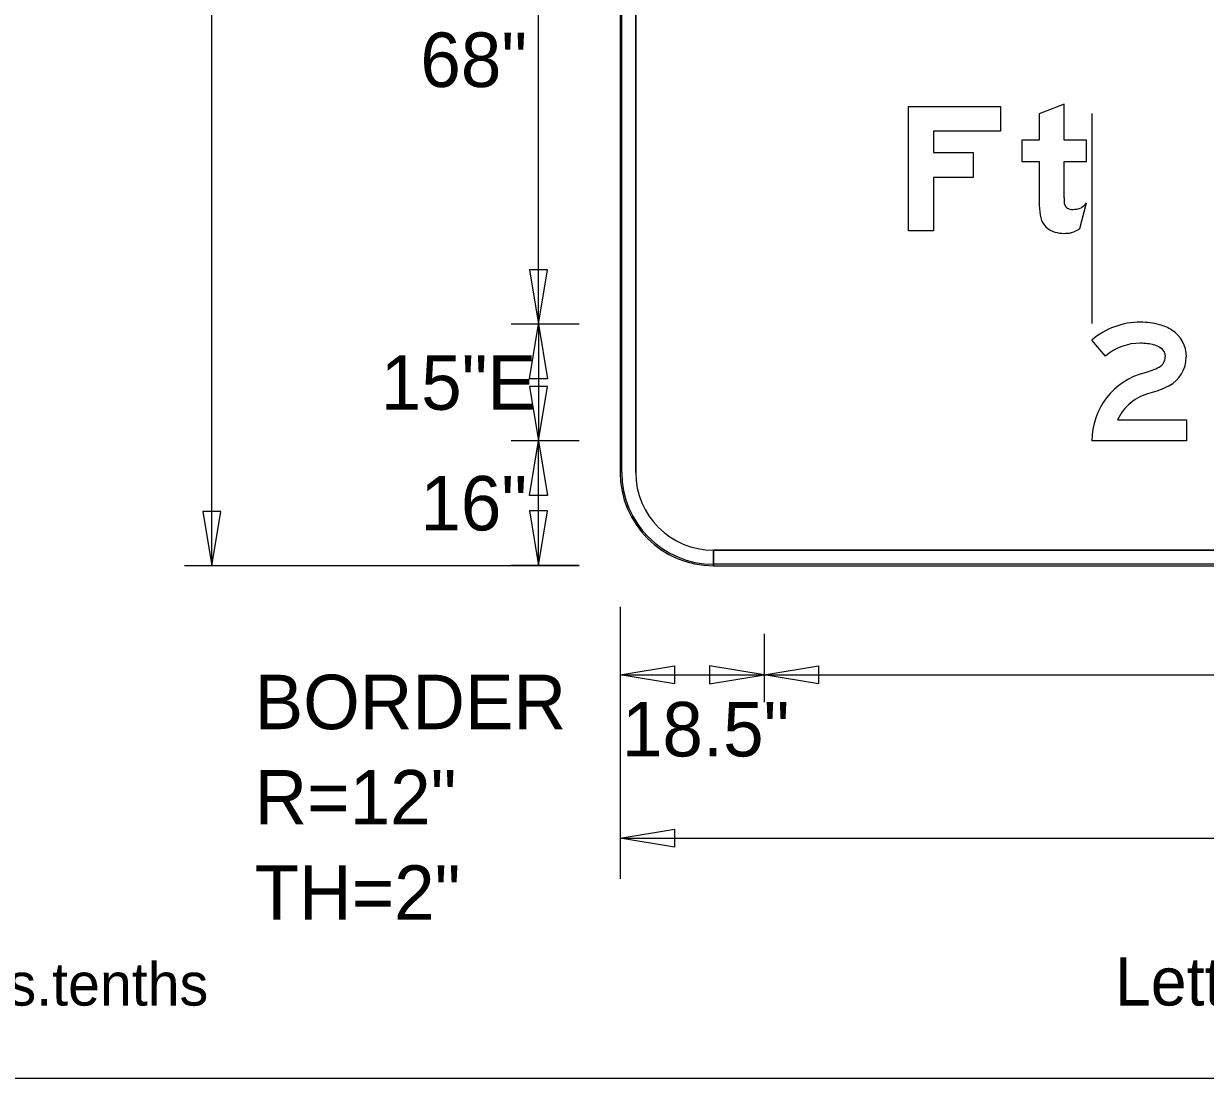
# Model space of a CAD drawing. Extents: x 2149961 to 2150220, y 145114 to 145240.
# Drawn here: x 2150025.13 to 2150037.79, y 145187.7 to 145199 of the extents above; entities that cross this region are included whole.
import ezdxf

# ---------------------------------------------------------------- set-up
doc = ezdxf.new("R2010")
doc.units = 0
for name, color, linetype in [('GSBWFILL', 7, 'Continuous'), ('GSCOLORFILL', 7, 'Continuous'), ('GSDIMS', 7, 'Continuous'), ('GSOUTLINE', 7, 'Continuous'), ('Level 1', 7, 'Continuous'), ('NON-PLOT', 7, 'Continuous')]:
    doc.layers.add(name, color=color, linetype=linetype)

msp = doc.modelspace()

# ---------------------------------------------------------------- linework, layer by layer
at = {"layer": 'GSBWFILL'}
for p, q in [((2150031.52, 145206.695), (2150031.52, 145194.195)), ((2150031.687, 145194.195), (2150031.687, 145206.695)), ((2150036.446, 145196.807), (2150036.516, 145197.083)), ((2150032.52, 145193.195), (2150032.52, 145193.361)), ((2150046.02, 145193.361), (2150032.522, 145193.361)), ((2150032.522, 145193.361), (2150032.522, 145193.195)), ((2150032.522, 145193.195), (2150046.02, 145193.195))]:
    msp.add_line(p, q, dxfattribs=at)
msp.add_lwpolyline([(2150034.609, 145198.116), (2150035.596, 145198.116), (2150035.596, 145197.849), (2150034.876, 145197.849), (2150034.876, 145197.622), (2150035.303, 145197.622), (2150035.303, 145197.356), (2150034.876, 145197.356), (2150034.876, 145196.782), (2150034.609, 145196.782)], close=True, dxfattribs=at)
for points in [[(2150036.276, 145197.136), (2150036.276, 145197.526), (2150036.516, 145197.526), (2150036.516, 145197.756), (2150036.276, 145197.756), (2150036.276, 145198.139), (2150036.009, 145198.038), (2150036.009, 145197.756), (2150035.823, 145197.756), (2150035.823, 145197.526), (2150036.009, 145197.526), (2150036.009, 145197.055)], [(2150036.719, 145195.441), (2150036.573, 145195.613)], [(2150036.848, 145194.757), (2150037.586, 145194.757), (2150037.586, 145194.532), (2150036.573, 145194.532)]]:
    msp.add_lwpolyline(points, dxfattribs=at)
for radius in [1, 0.833]:
    msp.add_arc((2150032.52, 145194.195), radius, 180, 270, dxfattribs=at)
for centre, major_axis, ratio, start_param, end_param in [((2150036.527, 145197.055), (0, 0.517), 0.999994, 1.570796, 1.830698), ((2150037.945, 145197.136), (0, 1.669), 0.999994, 1.570796, 1.606005), ((2150036.353, 145197.09), (0, 0.0767), 0.999994, 1.74085, 2.407828), ((2150036.355, 145197.093), (0, 0.0803), 0.999994, 2.407828, 3.141593), ((2150036.409, 145197.117), (0, 0.1), 0.999994, 3.310762, 3.756278), ((2150036.341, 145197.214), (0, 0.219), 0.999994, 3.756278, 4.071638), ((2150036.236, 145196.978), (0, 0.217), 0.999994, 1.830698, 2.869526), ((2150036.355, 145197.433), (0, 0.421), 0.999994, 3.141593, 3.310762), ((2150036.267, 145197.069), (0, 0.317), 0.999994, 3.427755, 3.738844), ((2150036.276, 145197.121), (0, 0.365), 0.999994, 2.869526, 3.141593), ((2150036.276, 145197.282), (0, 0.526), 0.999994, 3.141593, 3.205734), ((2150036.296, 145196.973), (0, 0.217), 0.999994, 3.205734, 3.427755), ((2150037.095, 145194.998), (0, 0.807), 0.999997, 0, 0.70376), ((2150037.095, 145195.014), (0, 0.79), 0.999997, 6.02311, 6.283185), ((2150037.18, 145195.335), (0, 0.458), 0.999997, 5.706931, 6.02311), ((2150037.244, 145195.433), (0, 0.342), 0.999997, 4.712389, 5.706931), ((2150037.095, 145194.998), (0, 0.582), 0.999997, 0, 0.70376), ((2150037.095, 145195.014), (0, 0.565), 0.999997, 6.02311, 6.283185), ((2150037.18, 145195.335), (0, 0.233), 0.999997, 5.706931, 6.02311), ((2150037.244, 145195.433), (0, 0.117), 0.999997, 4.712389, 5.706931), ((2150037.236, 145195.433), (0, 0.124), 0.999997, 3.626327, 4.712389), ((2150037.236, 145195.433), (0, 0.349), 0.999997, 3.626327, 4.712389), ((2150037.328, 145194.532), (0, 0.755), 0.999997, 0.25053, 1.570796), ((2150036.966, 145195.946), (0, 0.704), 0.999997, 3.392123, 3.626327), ((2150037.328, 145194.532), (0, 0.53), 0.999997, 0.25053, 1.132058), ((2150036.966, 145195.946), (0, 0.929), 0.999997, 3.392123, 3.626327)]:
    msp.add_ellipse(centre, major_axis=major_axis, ratio=ratio, start_param=start_param, end_param=end_param, dxfattribs=at)
at = {"layer": 'GSCOLORFILL'}
for p, q in [((2150031.52, 145206.695), (2150031.52, 145194.195)), ((2150031.52, 145206.695), (2150031.52, 145194.195)), ((2150031.52, 145206.695), (2150031.52, 145194.195)), ((2150031.537, 145194.195), (2150031.537, 145206.695)), ((2150031.687, 145194.195), (2150031.687, 145206.695)), ((2150036.446, 145196.807), (2150036.516, 145197.083)), ((2150032.52, 145193.195), (2150032.52, 145193.361)), ((2150046.02, 145193.361), (2150032.522, 145193.361)), ((2150032.522, 145193.361), (2150032.522, 145193.195)), ((2150032.52, 145193.195), (2150032.52, 145193.211)), ((2150046.02, 145193.211), (2150032.52, 145193.211)), ((2150032.52, 145193.211), (2150032.52, 145193.195)), ((2150032.52, 145193.195), (2150046.02, 145193.195)), ((2150032.52, 145193.195), (2150046.02, 145193.195)), ((2150032.522, 145193.195), (2150046.02, 145193.195))]:
    msp.add_line(p, q, dxfattribs=at)
msp.add_lwpolyline([(2150034.609, 145198.116), (2150035.596, 145198.116), (2150035.596, 145197.849), (2150034.876, 145197.849), (2150034.876, 145197.622), (2150035.303, 145197.622), (2150035.303, 145197.356), (2150034.876, 145197.356), (2150034.876, 145196.782), (2150034.609, 145196.782)], close=True, dxfattribs=at)
for points in [[(2150036.276, 145197.136), (2150036.276, 145197.526), (2150036.516, 145197.526), (2150036.516, 145197.756), (2150036.276, 145197.756), (2150036.276, 145198.139), (2150036.009, 145198.038), (2150036.009, 145197.756), (2150035.823, 145197.756), (2150035.823, 145197.526), (2150036.009, 145197.526), (2150036.009, 145197.055)], [(2150036.719, 145195.441), (2150036.573, 145195.613)], [(2150036.848, 145194.757), (2150037.586, 145194.757), (2150037.586, 145194.532), (2150036.573, 145194.532)]]:
    msp.add_lwpolyline(points, dxfattribs=at)
for radius in [1, 1, 1, 0.983, 0.833]:
    msp.add_arc((2150032.52, 145194.195), radius, 180, 270, dxfattribs=at)
for centre, major_axis, ratio, start_param, end_param in [((2150036.527, 145197.055), (0, 0.517), 0.999994, 1.570796, 1.830698), ((2150037.945, 145197.136), (0, 1.669), 0.999994, 1.570796, 1.606005), ((2150036.353, 145197.09), (0, 0.0767), 0.999994, 1.74085, 2.407828), ((2150036.355, 145197.093), (0, 0.0803), 0.999994, 2.407828, 3.141593), ((2150036.409, 145197.117), (0, 0.1), 0.999994, 3.310762, 3.756278), ((2150036.341, 145197.214), (0, 0.219), 0.999994, 3.756278, 4.071638), ((2150036.236, 145196.978), (0, 0.217), 0.999994, 1.830698, 2.869526), ((2150036.355, 145197.433), (0, 0.421), 0.999994, 3.141593, 3.310762), ((2150036.267, 145197.069), (0, 0.317), 0.999994, 3.427755, 3.738844), ((2150036.276, 145197.121), (0, 0.365), 0.999994, 2.869526, 3.141593), ((2150036.276, 145197.282), (0, 0.526), 0.999994, 3.141593, 3.205734), ((2150036.296, 145196.973), (0, 0.217), 0.999994, 3.205734, 3.427755), ((2150037.095, 145194.998), (0, 0.807), 0.999997, 0, 0.70376), ((2150037.095, 145195.014), (0, 0.79), 0.999997, 6.02311, 6.283185), ((2150037.18, 145195.335), (0, 0.458), 0.999997, 5.706931, 6.02311), ((2150037.244, 145195.433), (0, 0.342), 0.999997, 4.712389, 5.706931), ((2150037.095, 145194.998), (0, 0.582), 0.999997, 0, 0.70376), ((2150037.095, 145195.014), (0, 0.565), 0.999997, 6.02311, 6.283185), ((2150037.18, 145195.335), (0, 0.233), 0.999997, 5.706931, 6.02311), ((2150037.244, 145195.433), (0, 0.117), 0.999997, 4.712389, 5.706931), ((2150037.236, 145195.433), (0, 0.124), 0.999997, 3.626327, 4.712389), ((2150037.236, 145195.433), (0, 0.349), 0.999997, 3.626327, 4.712389), ((2150037.328, 145194.532), (0, 0.755), 0.999997, 0.25053, 1.570796), ((2150036.966, 145195.946), (0, 0.704), 0.999997, 3.392123, 3.626327), ((2150037.328, 145194.532), (0, 0.53), 0.999997, 0.25053, 1.132058), ((2150036.966, 145195.946), (0, 0.929), 0.999997, 3.392123, 3.626327)]:
    msp.add_ellipse(centre, major_axis=major_axis, ratio=ratio, start_param=start_param, end_param=end_param, dxfattribs=at)
at = {"layer": 'GSDIMS'}
for p, q in [((2150027.145, 145193.195), (2150027.145, 145207.695)), ((2150030.645, 145195.782), (2150030.645, 145201.449)), ((2150031.083, 145195.782), (2150030.353, 145195.782)), ((2150031.083, 145195.782), (2150030.353, 145195.782)), ((2150030.645, 145195.782), (2150030.645, 145194.532)), ((2150031.083, 145194.532), (2150030.353, 145194.532)), ((2150031.083, 145194.532), (2150030.353, 145194.532)), ((2150030.645, 145193.199), (2150030.645, 145194.532)), ((2150027.583, 145193.195), (2150026.853, 145193.195)), ((2150031.083, 145193.195), (2150027.583, 145193.195)), ((2150031.083, 145193.199), (2150030.353, 145193.199)), ((2150031.52, 145192.757), (2150031.52, 145189.841)), ((2150031.52, 145192.466), (2150031.52, 145191.736)), ((2150033.062, 145192.466), (2150033.062, 145191.736)), ((2150033.062, 145192.466), (2150033.062, 145191.736)), ((2150031.52, 145192.028), (2150033.062, 145192.028)), ((2150033.062, 145192.028), (2150045.478, 145192.028)), ((2150031.52, 145190.716), (2150031.52, 145189.986)), ((2150031.52, 145190.278), (2150047.02, 145190.278))]:
    msp.add_line(p, q, dxfattribs=at)
for points in [[(2150030.645, 145195.782), (2150030.742, 145196.366), (2150030.548, 145196.366)], [(2150030.645, 145195.782), (2150030.742, 145195.199), (2150030.548, 145195.199)], [(2150030.645, 145194.532), (2150030.742, 145195.116), (2150030.548, 145195.116)], [(2150030.645, 145194.532), (2150030.742, 145193.949), (2150030.548, 145193.949)], [(2150027.145, 145193.195), (2150027.242, 145193.778), (2150027.048, 145193.778)], [(2150030.645, 145193.199), (2150030.742, 145193.782), (2150030.548, 145193.782)], [(2150031.52, 145192.028), (2150032.103, 145192.125), (2150032.103, 145191.931)], [(2150033.062, 145192.028), (2150032.478, 145192.125), (2150032.478, 145191.931)], [(2150033.062, 145192.028), (2150033.645, 145192.125), (2150033.645, 145191.931)], [(2150031.52, 145190.278), (2150032.103, 145190.375), (2150032.103, 145190.181)]]:
    msp.add_lwpolyline(points, close=True, dxfattribs=at)
at = {"layer": 'GSOUTLINE'}
for p, q in [((2150031.52, 145206.695), (2150031.52, 145194.195)), ((2150031.687, 145206.695), (2150031.687, 145194.195)), ((2150036.446, 145196.807), (2150036.516, 145197.083)), ((2150032.52, 145193.361), (2150046.02, 145193.361)), ((2150032.52, 145193.195), (2150046.02, 145193.195))]:
    msp.add_line(p, q, dxfattribs=at)
msp.add_lwpolyline([(2150034.609, 145198.116), (2150035.596, 145198.116), (2150035.596, 145197.849), (2150034.876, 145197.849), (2150034.876, 145197.622), (2150035.303, 145197.622), (2150035.303, 145197.356), (2150034.876, 145197.356), (2150034.876, 145196.782), (2150034.609, 145196.782)], close=True, dxfattribs=at)
for points in [[(2150036.276, 145197.136), (2150036.276, 145197.526), (2150036.516, 145197.526), (2150036.516, 145197.756), (2150036.276, 145197.756), (2150036.276, 145198.139), (2150036.009, 145198.038), (2150036.009, 145197.756), (2150035.823, 145197.756), (2150035.823, 145197.526), (2150036.009, 145197.526), (2150036.009, 145197.055)], [(2150036.719, 145195.441), (2150036.573, 145195.613)], [(2150036.848, 145194.757), (2150037.586, 145194.757), (2150037.586, 145194.532), (2150036.573, 145194.532)]]:
    msp.add_lwpolyline(points, dxfattribs=at)
for radius in [1, 0.833]:
    msp.add_arc((2150032.52, 145194.195), radius, 180, 270, dxfattribs=at)
for centre, major_axis, ratio, start_param, end_param in [((2150036.527, 145197.055), (0, 0.517), 0.999994, 1.570796, 1.830698), ((2150037.945, 145197.136), (0, 1.669), 0.999994, 1.570796, 1.606005), ((2150036.353, 145197.09), (0, 0.0767), 0.999994, 1.74085, 2.407828), ((2150036.355, 145197.093), (0, 0.0803), 0.999994, 2.407828, 3.141593), ((2150036.409, 145197.117), (0, 0.1), 0.999994, 3.310762, 3.756278), ((2150036.341, 145197.214), (0, 0.219), 0.999994, 3.756278, 4.071638), ((2150036.236, 145196.978), (0, 0.217), 0.999994, 1.830698, 2.869526), ((2150036.355, 145197.433), (0, 0.421), 0.999994, 3.141593, 3.310762), ((2150036.267, 145197.069), (0, 0.317), 0.999994, 3.427755, 3.738844), ((2150036.276, 145197.121), (0, 0.365), 0.999994, 2.869526, 3.141593), ((2150036.276, 145197.282), (0, 0.526), 0.999994, 3.141593, 3.205734), ((2150036.296, 145196.973), (0, 0.217), 0.999994, 3.205734, 3.427755), ((2150037.095, 145194.998), (0, 0.807), 0.999997, 0, 0.70376), ((2150037.095, 145195.014), (0, 0.79), 0.999997, 6.02311, 6.283185), ((2150037.18, 145195.335), (0, 0.458), 0.999997, 5.706931, 6.02311), ((2150037.244, 145195.433), (0, 0.342), 0.999997, 4.712389, 5.706931), ((2150037.095, 145194.998), (0, 0.582), 0.999997, 0, 0.70376), ((2150037.095, 145195.014), (0, 0.565), 0.999997, 6.02311, 6.283185), ((2150037.18, 145195.335), (0, 0.233), 0.999997, 5.706931, 6.02311), ((2150037.244, 145195.433), (0, 0.117), 0.999997, 4.712389, 5.706931), ((2150037.236, 145195.433), (0, 0.124), 0.999997, 3.626327, 4.712389), ((2150037.236, 145195.433), (0, 0.349), 0.999997, 3.626327, 4.712389), ((2150037.328, 145194.532), (0, 0.755), 0.999997, 0.25053, 1.570796), ((2150036.966, 145195.946), (0, 0.704), 0.999997, 3.392123, 3.626327), ((2150037.328, 145194.532), (0, 0.53), 0.999997, 0.25053, 1.132058), ((2150036.966, 145195.946), (0, 0.929), 0.999997, 3.392123, 3.626327)]:
    msp.add_ellipse(centre, major_axis=major_axis, ratio=ratio, start_param=start_param, end_param=end_param, dxfattribs=at)
at = {"layer": 'Level 1'}
msp.add_line((2150017.557, 145187.705), (2150062.583, 145187.705), dxfattribs=at)
at = {"layer": 'NON-PLOT'}
for q in [(2150036.573, 145197.041), (2150036.573, 145195.791)]:
    msp.add_line((2150036.573, 145198.041), q, dxfattribs=at)

# ---------------------------------------------------------------- texts
at = {"layer": 'GSDIMS'}
for s, p in [('68"', (2150029.38, 145198.324)), ('15"E', (2150028.955, 145194.866)), ('16"', (2150029.38, 145193.574)), ('BORDER', (2150027.604, 145191.445)), ('18.5"', (2150031.539, 145191.153)), ('R=12"', (2150027.604, 145190.424)), ('TH=2"', (2150027.604, 145189.403))]:
    msp.add_text(s, height=0.5833, dxfattribs=at).set_placement(p)
at = {"layer": 'Level 1'}
for s, height, p in [('Dimensions are in: inches.tenths', 0.45913, (2150018.235, 145188.484)), ('Letter locations are panel edge to lower left corner', 0.51652, (2150036.821, 145188.485))]:
    msp.add_text(s, height=height, dxfattribs=at).set_placement(p)

doc.saveas('drawing.dxf')
